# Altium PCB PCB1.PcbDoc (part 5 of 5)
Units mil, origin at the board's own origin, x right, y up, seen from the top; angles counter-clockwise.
Board outline 4463 x 4481 mil, 2 copper layers (Top Layer, Bottom Layer); 0 components, 111 nets, 310 pads, 0 vias.
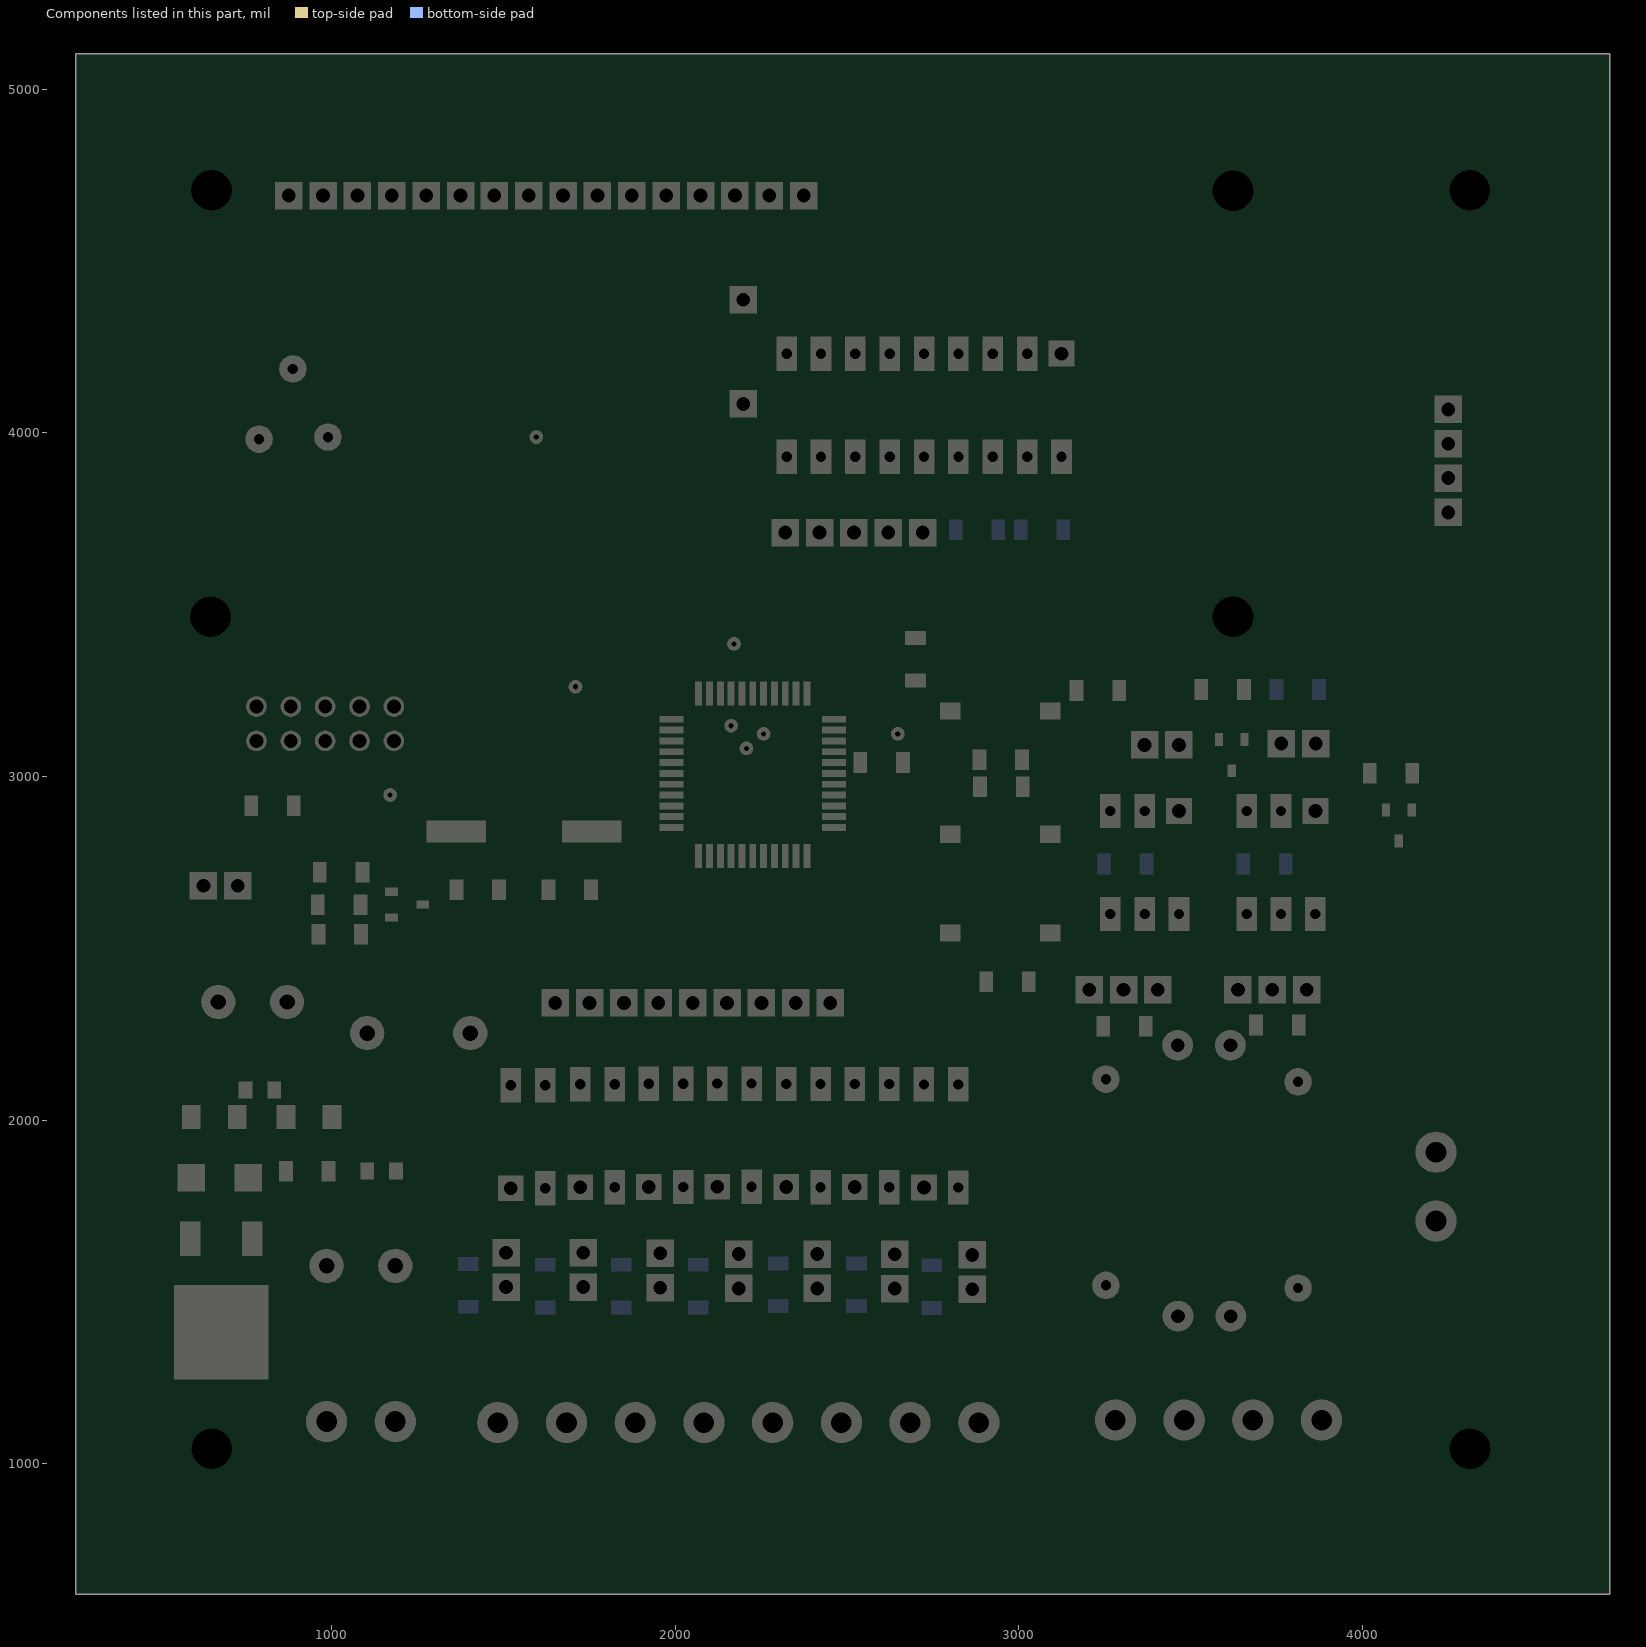
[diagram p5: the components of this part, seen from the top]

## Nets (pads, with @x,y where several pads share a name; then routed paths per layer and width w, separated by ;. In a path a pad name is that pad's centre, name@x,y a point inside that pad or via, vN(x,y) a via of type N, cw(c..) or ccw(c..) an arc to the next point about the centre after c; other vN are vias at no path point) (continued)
copper on no net: (continued)
  Bottom Layer w15: 3587.54,1581.9 3770.34,1581.9 ; 3587.54,1606.9 3770.34,1606.9 ; 3587.54,1631.9 3770.34,1631.9 ; 3587.54,1656.9 3770.34,1656.9 ; 3587.54,1681.9 3770.34,1681.9 ; 3587.54,1706.9 3770.34,1706.9 ; 3587.54,1731.9 3770.34,1731.9 ; 3587.54,1756.9 3770.34,1756.9 ; 3587.54,1781.9 3770.34,1781.9 ; 3587.54,1806.9 3770.34,1806.9 ; 3587.54,1831.9 3770.34,1831.9 ; 3587.54,1856.9 3770.34,1856.9 ; 3587.54,1881.9 3770.34,1881.9 ; 3587.54,1906.9 3770.34,1906.9 ; 3587.54,1931.9 3766.64,1931.9 ; 3587.54,1956.9 3741.64,1956.9 ; 3587.54,1981.9 3716.64,1981.9 ; 3587.54,2006.9 3691.64,2006.9 ; 3587.54,2031.9 3666.64,2031.9 ; 3587.54,2056.9 3641.64,2056.9 ; 3587.54,2081.9 3616.64,2081.9 ; 3587.54,2106.9 3591.64,2106.9 ; 3589.04,906.9 3589.04,1174.7 ; 3589.04,1517.7 3589.04,2109.6 ; 3589.04,2763.8 3589.04,3358.5 ; 3589.04,3571 3589.04,3623.4 ; 3589.04,4118.6 3589.04,4597.8 ; 3589.04,4810.3 3589.04,4841.9 ; 3596.24,1181.9 3612.44,1181.9 ; 3599.74,1506.9 3745.34,1506.9 ; 3614.04,906.9 3614.04,1070.6 ; 3614.04,1183.5 3614.04,1199.7 ; 3614.04,1502 3614.04,2084.6 ; 3614.04,2802.6 3614.04,2822 ; 3614.04,2976.9 3614.04,3358.5 ; 3614.04,3571 3614.04,3623.4 ; 3614.04,4118.6 3614.04,4597.8 ; 3614.04,4810.3 3614.04,4841.9 ; 3621.24,1206.9 3637.44,1206.9 ; 3639.04,906.9 3639.04,1045.6 ; 3639.04,1208.5 3639.04,1224.7 ; 3639.04,1502 3639.04,2059.6 ; 3639.04,2802.6 3639.04,2822 ; 3639.04,2976.9 3639.04,3358.5 ; 3639.04,3571 3639.04,3623.4 ; 3639.04,4118.6 3639.04,4597.8 ; 3639.04,4810.3 3639.04,4841.9 ; 3646.24,1231.9 3926.04,1231.9 ; 3659.64,1256.9 3951.04,1256.9 ; 3659.64,1281.9 3976.04,1281.9 ; 3659.64,1306.9 4001.04,1306.9 ; 3659.64,1331.9 4026.04,1331.9 ; 3659.64,1356.9 4051.04,1356.9 ; 3661.64,2281.9 3698.04,2281.9 ; 3661.94,2156.9 3710.64,2156.9 ; 3664.04,906.9 3664.04,1039.5 ; 3664.04,1214.5 3664.04,1373.8 ; 3664.04,1485.2 3664.04,2034.6 ; 3664.04,2154.8 3664.04,2163.2 ; 3664.04,2272.1 3664.04,2284.3 ; 3664.04,2802.6 3664.04,2822 ; 3664.04,2976.9 3664.04,3358.5 ; 3664.04,3571 3664.04,3623.4 ; 3664.04,4118.6 3664.04,4597.8 ; 3664.04,4810.3 3664.04,4841.9 ; 3667.24,1481.9 3746.74,1481.9 ; 3670.84,4806.9 4264.14,4806.9 ; 3672.14,1381.9 4076.04,1381.9 ; 3676.44,4606.9 4260.14,4606.9 ; 3679.14,2256.9 3698.04,2256.9 ; 3680.54,2306.9 3698.04,2306.9 ; 3681.54,3556.9 3714.84,3556.9 ; 3682.74,2181.9 3698.04,2181.9 ; 3686.94,2131.9 3735.64,2131.9 ; 3688.44,2206.9 3698.04,2206.9 ; 3688.44,2231.9 3698.04,2231.9 ; 3689.04,906.9 3689.04,1039.5 ; 3689.04,1214.5 3689.04,1398.8 ; 3689.04,1460.2 3689.04,2009.6 ; 3689.04,2129.8 3689.04,2311.5 ; 3689.04,2802.6 3689.04,2822 ; 3689.04,2976.9 3689.04,3380 ; 3689.04,3549.4 3689.04,3623.4 ; 3689.04,4118.6 3689.04,4619.4 ; 3689.04,4788.7 3689.04,4841.9 ; 3689.64,1406.9 4101.04,1406.9 ; 3689.64,1431.9 4126.04,1431.9 ; 3689.64,1456.9 3771.74,1456.9 ; 3690.84,3381.9 3714.84,3381.9 ; 3695.84,4781.9 4239.14,4781.9 ; 3700.84,2756.9 3716.04,2756.9 ; 3700.84,2781.9 3729.84,2781.9 ; 3701.44,4631.9 4235.14,4631.9 ; 3706.54,3531.9 3714.84,3531.9 ; 3711.94,2106.9 3745.34,2106.9 ; 3714.04,906.9 3714.04,1039.5 ; 3714.04,1214.5 3714.04,1984.6 ; 3714.04,2104.8 3714.04,2153.5 ; 3714.04,2754.9 3714.04,2822 ; 3714.04,2976.9 3714.04,3027.9 ; 3714.04,3162.9 3714.04,3195.4 ; 3714.04,3310.4 3714.04,3405 ; 3714.04,3524.4 3714.04,3623.4 ; 3714.04,4118.6 3714.04,4644.4 ; 3714.04,4763.7 3714.04,4841.9 ; 3720.84,4756.9 4214.14,4756.9 ; 3725.14,1206.9 3837.44,1206.9 ; 3726.44,4656.9 4210.14,4656.9 ; 3729.64,4681.9 4206.14,4681.9 ; 3729.64,4706.9 4206.14,4706.9 ; 3729.64,4731.9 4206.14,4731.9 ; 3734.94,1056.9 3827.64,1056.9 ; 3736.94,2081.9 3746.74,2081.9 ; 3739.04,906.9 3739.04,1061 ; 3739.04,1193 3739.04,1959.6 ; 3739.04,2079.8 3739.04,2128.5 ; 3739.04,2677 3739.04,2681 ; 3739.04,2802.6 3739.04,2822 ; 3739.04,2976.9 3739.04,3027.9 ; 3739.04,3167.6 3739.04,3195.4 ; 3739.04,4118.6 3739.04,4841.9 ; 3739.94,2681.9 4450.24,2681.9 ; 3750.14,1181.9 3812.44,1181.9 ; 3759.94,1081.9 3802.64,1081.9 ; 3761.94,2056.9 3771.74,2056.9 ; 3764.04,906.9 3764.04,1084.5 ; 3764.04,1169.5 3764.04,1464.6 ; 3764.04,1557.9 3764.04,1934.6 ; 3764.04,2054.8 3764.04,2064.6 ; 3764.04,2677 3764.04,2687.6 ; 3764.04,2802.6 3764.04,2822 ; 3764.04,2976.9 3764.04,3027.9 ; 3764.04,3192.6 3764.04,3195.4 ; 3764.04,4118.6 3764.04,4841.9 ; 3778.04,2206.9 4450.24,2206.9 ; 3778.04,2231.9 4450.24,2231.9 ; 3778.04,2256.9 4450.24,2256.9 ; 3778.04,2281.9 4450.24,2281.9 ; 3778.04,2306.9 4450.24,2306.9 ; 3783.84,4106.9 4182.34,4106.9 ; 3784.84,3331.9 4450.24,3331.9 ; 3784.84,3356.9 4450.24,3356.9 ; 3784.84,3381.9 4450.24,3381.9 ; 3784.84,3406.9 4450.24,3406.9 ; 3784.84,3431.9 4450.24,3431.9 ; 3784.84,3456.9 4450.24,3456.9 ; 3784.84,3481.9 4450.24,3481.9 ; 3784.84,3506.9 4450.24,3506.9 ; 3784.84,3531.9 4450.24,3531.9 ; 3784.84,3556.9 4450.24,3556.9 ; 3784.84,3581.9 4450.24,3581.9 ; 3786.94,2031.9 4028.84,2031.9 ; 3789.04,906.9 3789.04,1084.5 ; 3789.04,1169.5 3789.04,1443.8 ; 3789.04,2029.8 3789.04,2043.8 ; 3789.04,2191.6 3789.04,2311.5 ; 3789.04,2677 3789.04,2687.6 ; 3789.04,2802.6 3789.04,2822 ; 3789.04,2976.9 3789.04,3027.9 ; 3789.04,3310.4 3789.04,3589.1 ; 3789.04,4101.7 3789.04,4841.9 ; 3797.34,3231.9 3803.34,3231.9 ; 3797.34,3256.9 3826.34,3256.9 ; 3797.34,3281.9 3826.34,3281.9 ; 3797.34,3306.9 3826.34,3306.9 ; 3798.74,2181.9 4450.24,2181.9 ; 3806.84,3606.9 4450.24,3606.9 ; 3808.84,4081.9 4159.24,4081.9 ; 3811.94,2006.9 4053.84,2006.9 ; 3814.04,906.9 3814.04,1070.5 ; 3814.04,1183.5 3814.04,1443.8 ; 3814.04,2004.8 3814.04,2043.8 ; 3814.04,2178.8 3814.04,2311.5 ; 3814.04,2677 3814.04,2687.6 ; 3814.04,2802.6 3814.04,2822 ; 3814.04,2976.9 3814.04,3027.9 ; 3814.04,3242.6 3814.04,3614.1 ; 3814.04,4076.7 3814.04,4841.9 ; 3820.74,2831.9 4450.24,2831.9 ; 3824.84,2706.9 4450.24,2706.9 ; 3824.84,2731.9 4450.24,2731.9 ; 3824.84,2756.9 4450.24,2756.9 ; 3824.84,2781.9 4450.24,2781.9 ; 3833.84,4056.9 4140.04,4056.9 ; 3836.94,1981.9 4078.84,1981.9 ; 3839.04,906.9 3839.04,1045.5 ; 3839.04,1208.5 3839.04,1443.8 ; 3839.04,1979.8 3839.04,2043.8 ; 3839.04,2178.8 3839.04,2311.5 ; 3839.04,2677 3839.04,2834.5 ; 3839.04,3162.9 3839.04,3168.6 ; 3839.04,3310.4 3839.04,3623.4 ; 3839.04,4051.7 3839.04,4841.9 ; 3852.34,3181.9 4450.24,3181.9 ; 3853.84,1456.9 4151.04,1456.9 ; 3853.84,2056.9 4003.84,2056.9 ; 3855.34,1581.9 4171.84,1581.9 ; 3855.34,1606.9 4171.84,1606.9 ; 3855.34,1631.9 4165.24,1631.9 ; 3855.34,1656.9 4140.24,1656.9 ; 3855.34,1681.9 4126.84,1681.9 ; 3855.34,1706.9 4126.84,1706.9 ; 3855.34,1731.9 4126.84,1731.9 ; 3855.34,1756.9 4140.94,1756.9 ; 3855.34,1781.9 4165.94,1781.9 ; 3855.34,1806.9 4450.24,1806.9 ; 3855.34,1831.9 4165.24,1831.9 ; 3855.34,1856.9 4140.24,1856.9 ; 3855.34,1881.9 4126.84,1881.9 ; 3855.34,1906.9 4126.84,1906.9 ; 3855.34,1931.9 4126.84,1931.9 ; 3855.34,1956.9 4103.84,1956.9 ; 3858.84,4031.9 4140.04,4031.9 ; 3862.64,1556.9 4171.84,1556.9 ; 3862.64,2156.9 4450.24,2156.9 ; 3864.04,906.9 3864.04,1039.5 ; 3864.04,1214.5 3864.04,1467.1 ; 3864.04,1555.5 3864.04,2067.1 ; 3864.04,2155.5 3864.04,2311.5 ; 3864.04,2677 3864.04,2834.5 ; 3864.04,3162.9 3864.04,3193.6 ; 3864.04,3310.4 3864.04,3623.4 ; 3864.04,4026.7 3864.04,4841.9 ; 3878.84,1481.9 4171.84,1481.9 ; 3880.34,1506.9 4171.84,1506.9 ; 3880.34,1531.9 4171.84,1531.9 ; 3883.84,4006.9 4140.04,4006.9 ; 3889.04,906.9 3889.04,1039.5 ; 3889.04,1214.5 3889.04,2068.8 ; 3889.04,2153.8 3889.04,2311.5 ; 3889.04,2446.5 3889.04,2455.4 ; 3889.04,2677 3889.04,2834.5 ; 3889.04,3162.9 3889.04,3195.4 ; 3889.04,3310.4 3889.04,3623.4 ; 3889.04,4001.7 3889.04,4841.9 ; 3890.54,2456.9 4450.24,2456.9 ; 3898.24,2481.9 4450.24,2481.9 ; 3898.24,2506.9 4450.24,2506.9 ; 3898.24,2981.9 4450.24,2981.9 ; 3898.24,3006.9 4450.24,3006.9 ; 3905.54,2331.9 4450.24,2331.9 ; 3905.54,2356.9 4450.24,2356.9 ; 3905.54,2381.9 4450.24,2381.9 ; 3905.54,2406.9 4450.24,2406.9 ; 3905.54,2431.9 4450.24,2431.9 ; 3908.84,3981.9 4140.04,3981.9 ; 3914.04,906.9 3914.04,1039.5 ; 3914.04,1219.9 3914.04,2068.8 ; 3914.04,2153.8 3914.04,2522 ; 3914.04,2677 3914.04,2834.5 ; 3914.04,2964.4 3914.04,3027.9 ; 3914.04,3162.9 3914.04,3195.4 ; 3914.04,3310.4 3914.04,3623.4 ; 3914.04,3976.7 3914.04,4841.9 ; 3920.74,2531.9 4450.24,2531.9 ; 3920.74,2556.9 4450.24,2556.9 ; 3920.74,2581.9 4450.24,2581.9 ; 3920.74,2606.9 4450.24,2606.9 ; 3920.74,2631.9 4450.24,2631.9 ; 3920.74,2656.9 4450.24,2656.9 ; 3921.34,3206.9 4450.24,3206.9 ; 3921.34,3231.9 4450.24,3231.9 ; 3921.34,3256.9 4450.24,3256.9 ; 3921.34,3281.9 4450.24,3281.9 ; 3921.34,3306.9 4450.24,3306.9 ; 3928.24,2856.9 4450.24,2856.9 ; 3928.24,2881.9 4450.24,2881.9 ; 3928.24,2906.9 4450.24,2906.9 ; 3928.24,2931.9 4450.24,2931.9 ; 3928.24,2956.9 4450.24,2956.9 ; 3931.44,3031.9 4450.24,3031.9 ; 3931.44,3056.9 4450.24,3056.9 ; 3931.44,3081.9 4450.24,3081.9 ; 3931.44,3106.9 4450.24,3106.9 ; 3931.44,3131.9 4450.24,3131.9 ; 3931.44,3156.9 4450.24,3156.9 ; 3934.94,1056.9 4206.94,1056.9 ; 3939.04,906.9 3939.04,1061 ; 3939.04,1244.9 3939.04,2068.8 ; 3939.04,2153.8 3939.04,3623.4 ; 3939.04,3965.1 3939.04,4841.9 ; 3959.94,1081.9 4206.94,1081.9 ; 3964.04,906.9 3964.04,1086 ; 3964.04,1269.9 3964.04,2068.8 ; 3964.04,2153.8 3964.04,3623.4 ; 3964.04,3965.1 3964.04,4841.9 ; 3968.84,1106.9 4226.24,1106.9 ; 3968.84,1131.9 4251.24,1131.9 ; 3971.24,1156.9 4450.24,1156.9 ; 3989.04,906.9 3989.04,1174.7 ; 3989.04,1294.9 3989.04,2068.8 ; 3989.04,2153.8 3989.04,3623.4 ; 3989.04,3965.1 3989.04,4841.9 ; 3996.24,1181.9 4450.24,1181.9 ; 4014.04,906.9 4014.04,1199.7 ; 4014.04,1319.9 4014.04,2046.8 ; 4014.04,2153.8 4014.04,3623.4 ; 4014.04,3965.1 4014.04,4841.9 ; 4021.24,1206.9 4450.24,1206.9 ; 4039.04,906.9 4039.04,1224.7 ; 4039.04,1344.9 4039.04,2021.8 ; 4039.04,2142 4039.04,3623.4 ; 4039.04,3965.1 4039.04,4841.9 ; 4046.24,1231.9 4450.24,1231.9 ; 4049.04,2131.9 4450.24,2131.9 ; 4064.04,906.9 4064.04,1249.7 ; 4064.04,1369.9 4064.04,1996.8 ; 4064.04,2117 4064.04,3623.4 ; 4064.04,3965.1 4064.04,4841.9 ; 4071.24,1256.9 4450.24,1256.9 ; 4074.04,2106.9 4450.24,2106.9 ; 4089.04,906.9 4089.04,1274.7 ; 4089.04,1394.9 4089.04,1971.8 ; 4089.04,2092 4089.04,3623.4 ; 4089.04,3965.1 4089.04,4841.9 ; 4096.24,1281.9 4450.24,1281.9 ; 4099.04,2081.9 4450.24,2081.9 ; 4114.04,906.9 4114.04,1299.7 ; 4114.04,1419.9 4114.04,1946.8 ; 4114.04,2067 4114.04,3623.4 ; 4114.04,3965.1 4114.04,4841.9 ; 4121.24,1306.9 4450.24,1306.9 ; 4124.04,2056.9 4450.24,2056.9 ; 4139.04,906.9 4139.04,1324.7 ; 4139.04,1444.9 4139.04,1658.1 ; 4139.04,1755 4139.04,1858.1 ; 4139.04,2042 4139.04,3623.4 ; 4139.04,3967.2 4139.04,4841.9 ; 4146.24,1331.9 4450.24,1331.9 ; 4149.04,2031.9 4450.24,2031.9 ; 4164.04,906.9 4164.04,1349.7 ; 4164.04,1469.9 4164.04,1633.1 ; 4164.04,1780 4164.04,1833.1 ; 4164.04,2017 4164.04,3623.4 ; 4164.04,4086.7 4164.04,4841.9 ; 4171.24,1356.9 4450.24,1356.9 ; 4174.04,2006.9 4450.24,2006.9 ; 4189.04,906.9 4189.04,1374.7 ; 4189.04,1794 4189.04,1819 ; 4189.04,1994 4189.04,3623.4 ; 4189.04,4135.4 4189.04,4841.9 ; 4196.24,1381.9 4450.24,1381.9 ; 4214.04,906.9 4214.04,992.4 ; 4214.04,1094.7 4214.04,1399.7 ; 4214.04,1794 4214.04,1819 ; 4214.04,1994 4214.04,3623.4 ; 4214.04,4135.4 4214.04,4653 ; 4214.04,4756.7 4214.04,4841.9 ; 4221.24,1406.9 4450.24,1406.9 ; 4239.04,906.9 4239.04,967.4 ; 4239.04,1119.7 4239.04,1424.7 ; 4239.04,1794 4239.04,1819 ; 4239.04,1994 4239.04,3623.4 ; 4239.04,4212.9 4239.04,4628 ; 4239.04,4781.7 4239.04,4841.9 ; 4246.24,1431.9 4450.24,1431.9 ; 4256.84,1456.9 4450.24,1456.9 ; 4256.84,1481.9 4450.24,1481.9 ; 4256.84,1506.9 4450.24,1506.9 ; 4256.84,1531.9 4450.24,1531.9 ; 4256.84,1556.9 4450.24,1556.9 ; 4256.84,1581.9 4450.24,1581.9 ; 4256.84,1606.9 4450.24,1606.9 ; 4262.74,1781.9 4450.24,1781.9 ; 4262.74,1981.9 4450.24,1981.9 ; 4263.44,1631.9 4450.24,1631.9 ; 4263.44,1831.9 4450.24,1831.9 ; 4264.04,906.9 4264.04,942.4 ; 4264.04,1144.7 4264.04,1632.5 ; 4264.04,1780.6 4264.04,1832.5 ; 4264.04,1980.6 4264.04,3623.4 ; 4264.04,4232.8 4264.04,4603 ; 4264.04,4806.7 4264.04,4841.9 ; 4287.74,1756.9 4450.24,1756.9 ; 4287.74,1956.9 4450.24,1956.9 ; 4288.44,1656.9 4450.24,1656.9 ; 4288.44,1856.9 4450.24,1856.9 ; 4289.04,906.9 4289.04,937.3 ; 4289.04,1149.8 4289.04,1657.5 ; 4289.04,1755.6 4289.04,1857.5 ; 4289.04,1955.6 4289.04,3623.4 ; 4289.04,4232.8 4289.04,4598.6 ; 4289.04,4811.1 4289.04,4841.9 ; 4301.84,1681.9 4450.24,1681.9 ; 4301.84,1706.9 4450.24,1706.9 ; 4301.84,1731.9 4450.24,1731.9 ; 4301.84,1881.9 4450.24,1881.9 ; 4301.84,1906.9 4450.24,1906.9 ; 4301.84,1931.9 4450.24,1931.9 ; 4314.04,906.9 4314.04,937.3 ; 4314.04,1149.8 4314.04,3623.4 ; 4314.04,4232.8 4314.04,4598.6 ; 4314.04,4811.1 4314.04,4841.9 ; 4339.04,906.9 4339.04,937.3 ; 4339.04,1149.8 4339.04,3623.4 ; 4339.04,4232.8 4339.04,4598.6 ; 4339.04,4811.1 4339.04,4841.9 ; 4351.54,3631.9 4450.24,3631.9 ; 4355.74,4231.9 4450.24,4231.9 ; 4360.64,4806.9 4450.24,4806.9 ; 4364.04,906.9 4364.04,944.1 ; 4364.04,1143 4364.04,3644.4 ; 4364.04,4223.6 4364.04,4606.2 ; 4364.04,4803.5 4364.04,4841.9 ; 4364.64,4606.9 4450.24,4606.9 ; 4375.14,1131.9 4450.24,1131.9 ; 4376.54,3656.9 4450.24,3656.9 ; 4376.84,956.9 4450.24,956.9 ; 4380.74,4206.9 4450.24,4206.9 ; 4385.64,4781.9 4450.24,4781.9 ; 4389.04,906.9 4389.04,969.1 ; 4389.04,1118 4389.04,3669.4 ; 4389.04,4198.6 4389.04,4631.2 ; 4389.04,4778.5 4389.04,4841.9 ; 4389.64,4631.9 4450.24,4631.9 ; 4400.14,1106.9 4450.24,1106.9 ; 4401.54,3681.9 4450.24,3681.9 ; 4401.84,981.9 4450.24,981.9 ; 4402.94,3706.9 4450.24,3706.9 ; 4402.94,3731.9 4450.24,3731.9 ; 4402.94,3756.9 4450.24,3756.9 ; 4402.94,3781.9 4450.24,3781.9 ; 4402.94,3806.9 4450.24,3806.9 ; 4402.94,3831.9 4450.24,3831.9 ; 4402.94,3856.9 4450.24,3856.9 ; 4402.94,3881.9 4450.24,3881.9 ; 4402.94,3906.9 4450.24,3906.9 ; 4402.94,3931.9 4450.24,3931.9 ; 4402.94,3956.9 4450.24,3956.9 ; 4402.94,3981.9 4450.24,3981.9 ; 4402.94,4006.9 4450.24,4006.9 ; 4402.94,4031.9 4450.24,4031.9 ; 4402.94,4056.9 4450.24,4056.9 ; 4402.94,4081.9 4450.24,4081.9 ; 4402.94,4106.9 4450.24,4106.9 ; 4402.94,4131.9 4450.24,4131.9 ; 4402.94,4156.9 4450.24,4156.9 ; 4402.94,4181.9 4450.24,4181.9 ; 4410.64,4756.9 4450.24,4756.9 ; 4414.04,906.9 4414.04,994.1 ; 4414.04,1093 4414.04,4656.2 ; 4414.04,4753.5 4414.04,4841.9 ; 4414.64,4656.9 4450.24,4656.9 ; 4418.64,4681.9 4450.24,4681.9 ; 4418.64,4706.9 4450.24,4706.9 ; 4418.64,4731.9 4450.24,4731.9 ; 4419.44,1006.9 4450.24,1006.9 ; 4419.44,1031.9 4450.24,1031.9 ; 4419.44,1056.9 4450.24,1056.9 ; 4419.44,1081.9 4450.24,1081.9 ; 4439.04,906.9 4439.04,4841.9 ; 514.04,906.9 514.04,4841.9 ; 514.04,906.9 4450.24,906.9 ; 514.04,906.9 4450.24,906.9 ; 514.04,906.9 514.04,4841.9 ; 514.04,4841.9 4450.24,4841.9 ; 514.04,4841.9 4450.24,4841.9 ; 639.04,2266.1 593.64,2311.5 593.64,2360.9 581.44,2373.2 581.44,2614.6 560.34,2614.6 560.34,2749.6 592.84,2749.6 592.84,3133.5 648.84,3189.5 724.74,3189.5 724.74,3227.1 758.34,3260.8 806.04,3260.8 832.14,3234.6 858.34,3260.8 906.04,3260.8 932.14,3234.6 958.34,3260.8 1006.04,3260.8 1032.14,3234.6 1058.34,3260.8 1096.44,3260.8 1096.44,3358.3 1241.64,3503.6 1241.64,3952.2 1050.54,3952.2 1018.04,3919.7 962.14,3919.7 922.54,3959.2 922.54,4005.2 918.44,4009.2 857.14,4009.2 857.14,3953.3 817.64,3913.7 761.74,3913.7 722.14,3953.3 722.14,4009.2 754.64,4041.7 754.64,4452.4 836.94,4534.7 836.94,4622.4 808.44,4622.4 808.44,4757.4 840.94,4757.4 840.94,4759.5 885.04,4803.7 1268.34,4803.7 1310.94,4761.1 1310.94,4757.4 2441.84,4757.4 2441.84,4622.4 1909.34,4622.4 1909.34,4453.4 1828.24,4372.3 1828.24,3420.6 2139.34,3420.6 2151.84,3433.1 2191.24,3433.1 2219.04,3405.3 2219.04,3365.9 2191.24,3338.1 2151.84,3338.1 2139.34,3350.6 1849.84,3350.6 1758.04,3258.8 1758.04,3241.1 1730.24,3213.3 1690.84,3213.3 1663.04,3241.1 1663.04,3280.5 1690.84,3308.3 1708.54,3308.3 1716.64,3316.3 1232.14,3316.3 1217.14,3301.4 1217.14,3249.6 1239.64,3227.1 1239.64,3179.5 1213.54,3153.3 1239.64,3127.1 1239.64,3079.5 1206.04,3045.8 1158.34,3045.8 1132.14,3072 1106.04,3045.8 1058.34,3045.8 1032.14,3072 1006.04,3045.8 958.34,3045.8 932.14,3072 906.04,3045.8 858.34,3045.8 832.14,3072 806.04,3045.8 758.34,3045.8 724.74,3079.5 724.74,3119.5 677.74,3119.5 662.84,3104.5 662.84,2749.6 795.34,2749.6 795.34,2614.6 666.44,2614.6 666.44,2421.1 703.24,2421.1 748.64,2375.7 748.64,2311.5 703.24,2266.1 639.04,2266.1 ; 839.04,2266.1 793.64,2311.5 793.64,2375.7 839.04,2421.1 ; 839.04,2266.1 903.24,2266.1 948.64,2311.5 948.64,2375.7 903.24,2421.1 839.04,2421.1 ; 4450.24,906.9 4450.24,4841.9 ; 4450.24,906.9 4450.24,4841.9 ; 542.14,3420.3 604.34,3358.1 692.34,3358.1 754.54,3420.3 754.54,3508.3 692.34,3570.6 604.34,3570.6 542.14,3508.3 542.14,3420.3 ; 545.24,4661.7 607.44,4599.4 695.44,4599.4 757.74,4661.7 757.74,4749.7 695.44,4811.9 607.44,4811.9 545.24,4749.7 545.24,4661.7 ; 546.04,999.5 608.24,937.3 696.24,937.3 758.54,999.5 758.54,1087.6 696.24,1149.8 608.24,1149.8 546.04,1087.6 546.04,999.5 ; 898.64,1086.8 898.64,1159.3 943.64,1204.3 943.64,1508.7 908.64,1543.7 908.64,1607.9 954.04,1653.3 1018.24,1653.3 1063.64,1607.9 1063.64,1543.7 1028.64,1508.7 1028.64,1204.3 1073.64,1159.3 1073.64,1086.8 1027.44,1040.7 1027.44,1040 1145.44,1040 1098.64,1086.8 1098.64,1159.3 1143.64,1204.3 1143.64,1508.7 1108.64,1543.7 1108.64,1607.9 1154.04,1653.3 1218.24,1653.3 1263.64,1607.9 1263.64,1549 1340.84,1549 1340.84,1628.5 1363.34,1628.5 1363.34,1777.7 1422.04,1836.4 1457.34,1836.4 1457.34,1866.4 1564.84,1866.4 1564.84,1878.9 1679.84,1878.9 1679.84,1869.6 1766.84,1869.6 1766.84,1882.1 1881.84,1882.1 1881.84,1870.4 1966.04,1870.4 1966.04,1882.9 2081.04,1882.9 2081.04,1871.2 2165.24,1871.2 2165.24,1883.7 2280.24,1883.7 2280.24,1870 2366.04,1870 2366.04,1882.5 2481.04,1882.5 2481.04,1870 2565.54,1870 2565.54,1882.5 2680.54,1882.5 2680.54,1868.8 2766.74,1868.8 2766.74,1881.3 2881.74,1881.3 2881.74,1726.3 2859.24,1726.3 2859.24,1717.5 2899.74,1676.9 2899.74,1675.2 2932.24,1675.2 2932.24,1553.5 2934.54,1555.7 2934.54,1968.4 2832.24,1968.4 2824.14,1976.5 2817.44,1969.8 2631.74,1969.8 2622.34,1979.3 2613.94,1970.9 2428.74,1970.9 2422.54,1977.1 2414.44,1969 2228.34,1969 2221.44,1975.8 2218.34,1972.7 2031.44,1972.7 2023.54,1980.7 2017.54,1974.7 1830.64,1974.7 1822.74,1982.6 1815.54,1975.5 1633.04,1975.5 1587.34,2021.2 1587.34,2023.9 1464.84,2023.9 1464.84,2178.9 1489.34,2178.9 1489.34,2241.5 1542.84,2295.1 1583.94,2295.1 1583.94,2408.3 2518.84,2408.3 2518.84,2273.3 2409.84,2273.3 2424.24,2258.9 2681.64,2258.9 2759.24,2181.3 2881.74,2181.3 2881.74,2038.4 2970.24,2038.4 3004.54,2004.1 3004.54,1526.7 2950.54,1472.7 2932.24,1472.7 2932.24,1440.2 2804.54,1440.2 2804.54,1405.9 2782.04,1405.9 2782.04,1271.4 2846.94,1206.6 2847.84,1207.4 2920.34,1207.4 2971.54,1156.2 2971.54,1083.7 2920.34,1032.4 2847.84,1032.4 2796.54,1083.7 2796.54,1156.2 2797.44,1157.1 2712.04,1242.4 2712.04,1405.9 2689.54,1405.9 2689.54,1442.2 2585.64,1442.2 2585.64,1411.4 2563.14,1411.4 2563.14,1290.3 2646.94,1206.6 2647.84,1207.4 2720.34,1207.4 2771.54,1156.2 2771.54,1083.7 2720.34,1032.4 2647.84,1032.4 2596.54,1083.7 2596.54,1156.2 2597.44,1157.1 2493.14,1261.3 2493.14,1411.4 2470.74,1411.4 2470.74,1442.6 2357.44,1442.6 2357.44,1411.4 2334.94,1411.4 2334.94,1318.7 2447.04,1206.6 2447.94,1207.4 2520.34,1207.4 2571.54,1156.2 2571.54,1083.7 2520.34,1032.4 2447.94,1032.4 2396.64,1083.7 2396.64,1156.2 2397.54,1157.1 2264.94,1289.7 2264.94,1411.4 2242.44,1411.4 2242.44,1442.6 2125.14,1442.6 2125.14,1407.5 2101.84,1407.5 2101.84,1351.8 2247.04,1206.6 2247.94,1207.4 2320.44,1207.4 2371.64,1156.2 2371.64,1083.7 2320.44,1032.4 2247.94,1032.4 2196.64,1083.7 2196.64,1156.2 2197.54,1157.1 2031.84,1322.8 2031.84,1407.5 2010.14,1407.5 2010.14,1445 1900.74,1445 1900.74,1407.5 1878.64,1407.5 1878.64,1375 2047.04,1206.6 2047.94,1207.4 2120.44,1207.4 2171.64,1156.2 2171.64,1083.7 2120.44,1032.4 2047.94,1032.4 1996.64,1083.7 1996.64,1156.2 1997.54,1157.1 1808.64,1346 1808.64,1407.5 1785.74,1407.5 1785.74,1446.5 1680.24,1446.5 1680.24,1407.5 1657.74,1407.5 1657.74,1396.6 1839.54,1214.8 1839.64,1214.8 1847.44,1207 1847.94,1207.4 1920.44,1207.4 1971.64,1156.2 1971.64,1083.7 1920.44,1032.4 1847.94,1032.4 1796.64,1083.7 1796.64,1156.2 1797.94,1157.4 1587.74,1367.6 1587.74,1407.5 1565.24,1407.5 1565.24,1446.5 1455.84,1446.5 1455.84,1409.5 1444.14,1409.5 1647.04,1206.6 1647.94,1207.4 1720.44,1207.4 1771.64,1156.2 1771.64,1083.7 1720.44,1032.4 1647.94,1032.4 1596.64,1083.7 1596.64,1156.2 1597.54,1157.1 1364.94,1389.7 1364.94,1409.5 1340.84,1409.5 1340.84,1479 1233.44,1479 1228.64,1483.8 1228.64,1204.3 1273.64,1159.3 1273.64,1086.8 1226.74,1040 1426.84,1040 1433.54,1046.8 1396.64,1083.7 1396.64,1156.2 1447.94,1207.4 1520.44,1207.4 1571.64,1156.2 1571.64,1083.7 1526.64,1038.7 1526.64,1019.7 1462.04,955 988.24,955 942.44,1000.8 942.44,1043 898.64,1086.8 ; 1026.74,2220.9 1026.74,2285.1 1072.14,2330.5 1136.34,2330.5 1181.74,2285.1 1181.74,2220.9 1136.34,2175.5 1072.14,2175.5 1026.74,2220.9 ; 1123.64,2926.1 1123.64,2965.5 1151.54,2993.3 1169.14,2993.3 1211.74,3035.9 1518.84,3035.9 1665.34,3182.4 2131.14,3182.4 2143.64,3194.9 2182.94,3194.9 2210.84,3167.1 2210.84,3144 2238.14,3171.3 2277.44,3171.3 2289.94,3158.8 2616.04,3158.8 2628.54,3171.3 2667.94,3171.3 2695.74,3143.4 2695.74,3116.6 2729.44,3116.6 3094.74,3482 3094.74,3660 3082.24,3660 3082.24,3715.5 3053.24,3744.5 3053.24,3660 3040.74,3660 3040.74,3624.2 3000.54,3584 2723.54,3584 2683.34,3624.2 2683.34,3642.1 2253.24,3642.1 2253.24,3777.1 2285.74,3777.1 2285.74,3852.6 2267.24,3852.6 2267.24,4007.6 2689.64,4007.6 2689.64,4019.4 2696.34,4026.1 2266.24,4026.1 2266.24,4016.1 2131.24,4016.1 2131.24,4151.1 2266.24,4151.1 2266.24,4141.1 3281.54,4141.1 3304.04,4118.6 3772.14,4118.6 3925.74,3965.1 4136.84,3965.1 4140.04,3968.2 4140.04,4062.7 4180.24,4102.9 4182.34,4102.9 4182.34,4135.4 4214.84,4135.4 4214.84,4188.7 4258.94,4232.8 4354.84,4232.8 4382.44,4205.2 4402.94,4184.7 4402.94,3683.3 4343.04,3623.4 3823.34,3623.4 3784.84,3584.9 3784.84,3310.4 3797.34,3310.4 3797.34,3225.9 3826.34,3254.9 3826.34,3310.4 3921.34,3310.4 3921.34,3195.4 3865.84,3195.4 3833.34,3162.9 3931.44,3162.9 3931.44,3027.9 3898.24,3027.9 3898.24,2964.4 3928.24,2964.4 3928.24,2834.5 3820.74,2834.5 3820.74,2822 3605.74,2822 3605.74,2976.9 3820.74,2976.9 3820.74,2964.4 3828.24,2964.4 3828.24,3027.9 3696.44,3027.9 3696.44,3162.9 3734.34,3162.9 3766.84,3195.4 3702.34,3195.4 3702.34,3310.4 3714.84,3310.4 3714.84,3405.8 3667.44,3358.5 3579.44,3358.5 3517.14,3420.7 3517.14,3508.7 3579.44,3571 3667.44,3571 3714.84,3523.6 3714.84,3613.9 3724.34,3623.4 3434.54,3623.4 3182.14,3875.8 3182.14,3852.6 3059.64,3852.6 3059.64,3837.1 3121.74,3775 3177.24,3775 3177.24,3660 3164.74,3660 3164.74,3453 2758.44,3046.6 2239.94,3046.6 2227.44,3034.1 2188.14,3034.1 2160.24,3062 2160.24,3099.9 2143.64,3099.9 2131.14,3112.4 1694.34,3112.4 1547.84,2965.9 1240.74,2965.9 1218.64,2943.8 1218.64,2926.1 1190.84,2898.3 1151.54,2898.3 1123.64,2926.1 ; 1326.74,2220.9 1326.74,2285.1 1372.14,2330.5 1436.34,2330.5 1481.74,2285.1 1481.74,2220.9 1436.34,2175.5 1372.14,2175.5 1326.74,2220.9 ; 2131.24,4319.3 2131.24,4454.3 2266.24,4454.3 2266.24,4444.3 3311.04,4444.3 3344.74,4410.6 3344.74,4362.9 3311.04,4329.3 2266.24,4329.3 2266.24,4319.3 2233.74,4319.3 2233.74,4283.9 2252.64,4265.1 2267.24,4265.1 2267.24,4307.6 3082.14,4307.6 3082.14,4295.1 3189.64,4295.1 3189.64,4165.1 3082.14,4165.1 3082.14,4152.6 2267.24,4152.6 2267.24,4195.1 2223.64,4195.1 2163.74,4254.9 2163.74,4319.3 2131.24,4319.3 ; 3120.74,1455.2 3120.74,2223.4 3162.44,2265.1 3162.44,2311.5 3137.44,2311.5 3137.44,2446.5 3246.94,2446.5 3155.74,2537.7 3155.74,2739.9 3195.94,2780.1 3200.34,2780.1 3200.34,2802.6 3295.34,2802.6 3295.34,2745.7 3324.34,2774.7 3324.34,2802.6 3419.34,2802.6 3419.34,2687.6 3336.34,2687.6 3325.64,2677 3523.84,2677 3523.84,2522 3501.34,2522 3501.34,2482.4 3540.34,2521.3 3565.24,2521.3 3565.24,2739.9 3605.34,2780.1 3605.84,2780.1 3605.84,2802.6 3700.84,2802.6 3700.84,2741.7 3729.84,2770.7 3729.84,2802.6 3824.84,2802.6 3824.84,2687.6 3745.74,2687.6 3735.04,2677 3920.74,2677 3920.74,2522 3898.24,2522 3898.24,2464.5 3880.14,2446.5 3905.54,2446.5 3905.54,2311.5 3778.04,2311.5 3778.04,2202.6 3801.84,2178.8 3840.74,2178.8 3865.74,2153.8 4027.24,2153.8 4186.94,1994 4250.64,1994 4301.84,1942.8 4301.84,1870.3 4250.64,1819 4178.14,1819 4126.84,1870.3 4126.84,1933.9 3992.04,2068.8 3865.74,2068.8 3840.74,2043.8 3784.84,2043.8 3745.34,2083.3 3745.34,2122.2 3698.04,2169.5 3698.04,2311.5 3680.54,2311.5 3680.54,2300.8 3657.94,2278.2 3688.44,2247.6 3688.44,2187.5 3659.84,2159 3855.34,1963.5 3855.34,1564.2 3880.34,1539.2 3880.34,1483.3 3840.74,1443.8 3784.84,1443.8 3745.34,1483.3 3745.34,1539.2 3770.34,1564.2 3770.34,1928.3 3587.54,2111 3587.54,1519.1 3604.74,1502 3647.24,1502 3689.64,1459.5 3689.64,1399.4 3659.64,1369.4 3659.64,1245.3 3568.84,1154.4 3568.84,1090.8 3517.54,1039.5 3445.04,1039.5 3393.84,1090.8 3393.84,1163.3 3445.04,1214.5 3508.74,1214.5 3574.64,1280.5 3574.64,1369.4 3544.64,1399.4 3544.64,1441.9 3536.14,1450.4 3536.14,1399.4 3506.14,1369.4 3506.14,1291.7 3368.84,1154.4 3368.84,1090.8 3317.54,1039.5 3245.04,1039.5 3193.84,1090.8 3193.84,1163.3 3245.04,1214.5 3308.74,1214.5 3421.14,1326.9 3421.14,1369.4 3403.64,1387 3188.94,1387 3120.74,1455.2 ; 3208.84,2822 3208.84,2976.9 3423.84,2976.9 3423.84,2964.4 3431.34,2964.4 3431.34,3024 3298.84,3024 3298.84,3159 3533.84,3159 3533.84,3024 3501.34,3024 3501.34,2964.4 3531.34,2964.4 3531.34,2834.5 3423.84,2834.5 3423.84,2822 3208.84,2822 ; 3517.14,4660.1 3579.44,4597.8 3667.44,4597.8 3729.64,4660.1 3729.64,4748.1 3667.44,4810.3 3579.44,4810.3 3517.14,4748.1 3517.14,4660.1 ; 3593.84,1090.8 3593.84,1163.3 3645.04,1214.5 3717.54,1214.5 3762.54,1169.5 3800.04,1169.5 3845.04,1214.5 3908.74,1214.5 4171.84,1477.7 4171.84,1625.3 4126.84,1670.3 4126.84,1742.8 4178.14,1794 4250.64,1794 4301.84,1742.8 4301.84,1670.3 4256.84,1625.3 4256.84,1442.5 3968.84,1154.4 3968.84,1090.8 3917.54,1039.5 3845.04,1039.5 3800.04,1084.5 3762.54,1084.5 3717.54,1039.5 3645.04,1039.5 3593.84,1090.8 ; 4206.14,4660.9 4268.44,4598.6 4356.44,4598.6 4418.64,4660.9 4418.64,4748.9 4356.44,4811.1 4268.44,4811.1 4206.14,4748.9 4206.14,4660.9 ; 4206.94,999.5 4269.14,937.3 4357.24,937.3 4419.44,999.5 4419.44,1087.6 4357.24,1149.8 4269.14,1149.8 4206.94,1087.6 4206.94,999.5

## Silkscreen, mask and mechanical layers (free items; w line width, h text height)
Top Overlay:
  drawing of 2528 lines, arcs and shapes, not listed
